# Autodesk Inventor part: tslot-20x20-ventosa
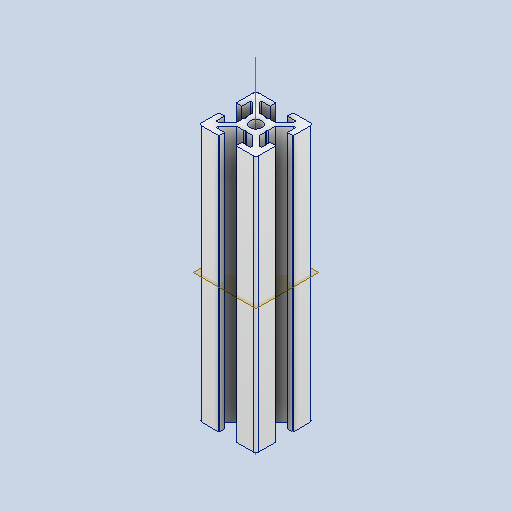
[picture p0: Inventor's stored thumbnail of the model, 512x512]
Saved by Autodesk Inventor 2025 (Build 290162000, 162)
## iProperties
Created: 2025-03
Part Number: tslot-20x20-ventosa
Material: Alluminio 6061
Document SubType Name: Modeling
Designer: Ryzen5700u
Density: 2.7 g/cm^3
Appearance: Alluminio - Piatto
Author: Ryzen5700u
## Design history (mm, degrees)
feature "Base1"
sketch "Schizzo1"
  geometry: L1 (3.761, -16)-(4.7, -16) reference; L2 (3.761, -16)-(0.7, -12.939) reference; L3 (0.7, -12.939)-(0.7, -10.52) reference; L4 (0.4, -10)-(0.7, -10.52) reference; L5 (0.4, -10)-(0.7, -9.48) reference; L6 (0.7, -7.061)-(0.7, -9.48) reference; L7 (3.761, -4)-(0.7, -7.061) reference; L8 (3.761, -4)-(4.7, -4) reference; L9 (4.7, -4)-(4.7, -7) reference; L10 (4.7, -7)-(6.4, -7) reference; L11 (6.7, -6.7)-(6.7, -1) reference; L12 (5.7, 0)-(0, 0) reference; L13 (-0.3, -2)-(-0.3, -0.3) reference; L14 (2.7, -2)-(-0.3, -2) reference; L15 (2.7, -2.939)-(2.7, -2) reference; L16 (2.7, -2.939)-(-0.361, -6) reference; L17 (-0.361, -6)-(-2.78, -6) reference; L18 (-3.3, -6.3)-(-2.78, -6) reference; L19 (-3.3, -6.3)-(-3.82, -6) reference; L20 (-6.239, -6)-(-3.82, -6) reference; L21 (-9.3, -2.939)-(-6.239, -6) reference; L22 (-9.3, -2.939)-(-9.3, -2) reference; L23 (-9.3, -2)-(-6.3, -2) reference; L24 (-6.3, -2)-(-6.3, -0.3) reference; L25 (-12.3, 0)-(-6.6, 0) reference; L26 (-13.3, -6.7)-(-13.3, -1) reference; L27 (-11.3, -7)-(-13, -7) reference; L28 (-11.3, -4)-(-11.3, -7) reference; L29 (-10.361, -4)-(-11.3, -4) reference; L30 (-10.361, -4)-(-7.3, -7.061) reference; L31 (-7.3, -7.061)-(-7.3, -9.48) reference; L32 (-7, -10)-(-7.3, -9.48) reference; L33 (-7, -10)-(-7.3, -10.52) reference; L34 (-7.3, -12.939)-(-7.3, -10.52) reference; L35 (-10.361, -16)-(-7.3, -12.939) reference; L36 (-10.361, -16)-(-11.3, -16) reference; L37 (-11.3, -16)-(-11.3, -13) reference; L38 (-11.3, -13)-(-13, -13) reference; L39 (-13.3, -13.3)-(-13.3, -19) reference; L40 (-12.3, -20)-(-6.6, -20) reference; L41 (-6.3, -18)-(-6.3, -19.7) reference; L42 (-9.3, -18)-(-6.3, -18) reference; L43 (-9.3, -17.061)-(-9.3, -18) reference; L44 (-9.3, -17.061)-(-6.239, -14) reference; L45 (-6.239, -14)-(-3.82, -14) reference; L46 (-3.3, -13.7)-(-3.82, -14) reference; L47 (-3.3, -13.7)-(-2.78, -14) reference; L48 (-0.361, -14)-(-2.78, -14) reference; L49 (2.7, -17.061)-(-0.361, -14) reference; L50 (2.7, -17.061)-(2.7, -18) reference; L51 (2.7, -18)-(-0.3, -18) reference; L52 (-0.3, -18)-(-0.3, -19.7) reference; L53 (5.7, -20)-(0, -20) reference; L54 (6.7, -13.3)-(6.7, -19) reference; L55 (4.7, -13)-(6.4, -13) reference; L56 (4.7, -16)-(4.7, -13) reference; C1 r 2.1 at (-3.3, -10) reference; A1 r 0.3 centre (6.4, -6.7) between (6.4, -7) and (6.7, -6.7) reference; A2 r 1 centre (5.7, -1) between (6.7, -1) and (5.7, 0) reference; A3 r 0.3 centre (0, -0.3) between (0, 0) and (-0.3, -0.3) reference; A4 r 0.3 centre (-6.6, -0.3) between (-6.3, -0.3) and (-6.6, 0) reference; A5 r 1 centre (-12.3, -1) between (-12.3, 0) and (-13.3, -1) reference; A6 r 0.3 centre (-13, -6.7) between (-13.3, -6.7) and (-13, -7) reference; A7 r 0.3 centre (-13, -13.3) between (-13, -13) and (-13.3, -13.3) reference; A8 r 1 centre (-12.3, -19) between (-13.3, -19) and (-12.3, -20) reference; A9 r 0.3 centre (-6.6, -19.7) between (-6.6, -20) and (-6.3, -19.7) reference; A10 r 0.3 centre (0, -19.7) between (-0.3, -19.7) and (0, -20) reference; A11 r 1 centre (5.7, -19) between (5.7, -20) and (6.7, -19) reference; A12 r 0.3 centre (6.4, -13.3) between (6.7, -13.3) and (6.4, -13) reference; 1 further point
extrude "Estrusione1" join sketch "Schizzo1" distance "d0" = 80; taper "d1" = 0 deg
node "Piano di lavoro1"
node "Asse di lavoro1"
node "Solido1"
node "Linea chiusa proiettata1"
